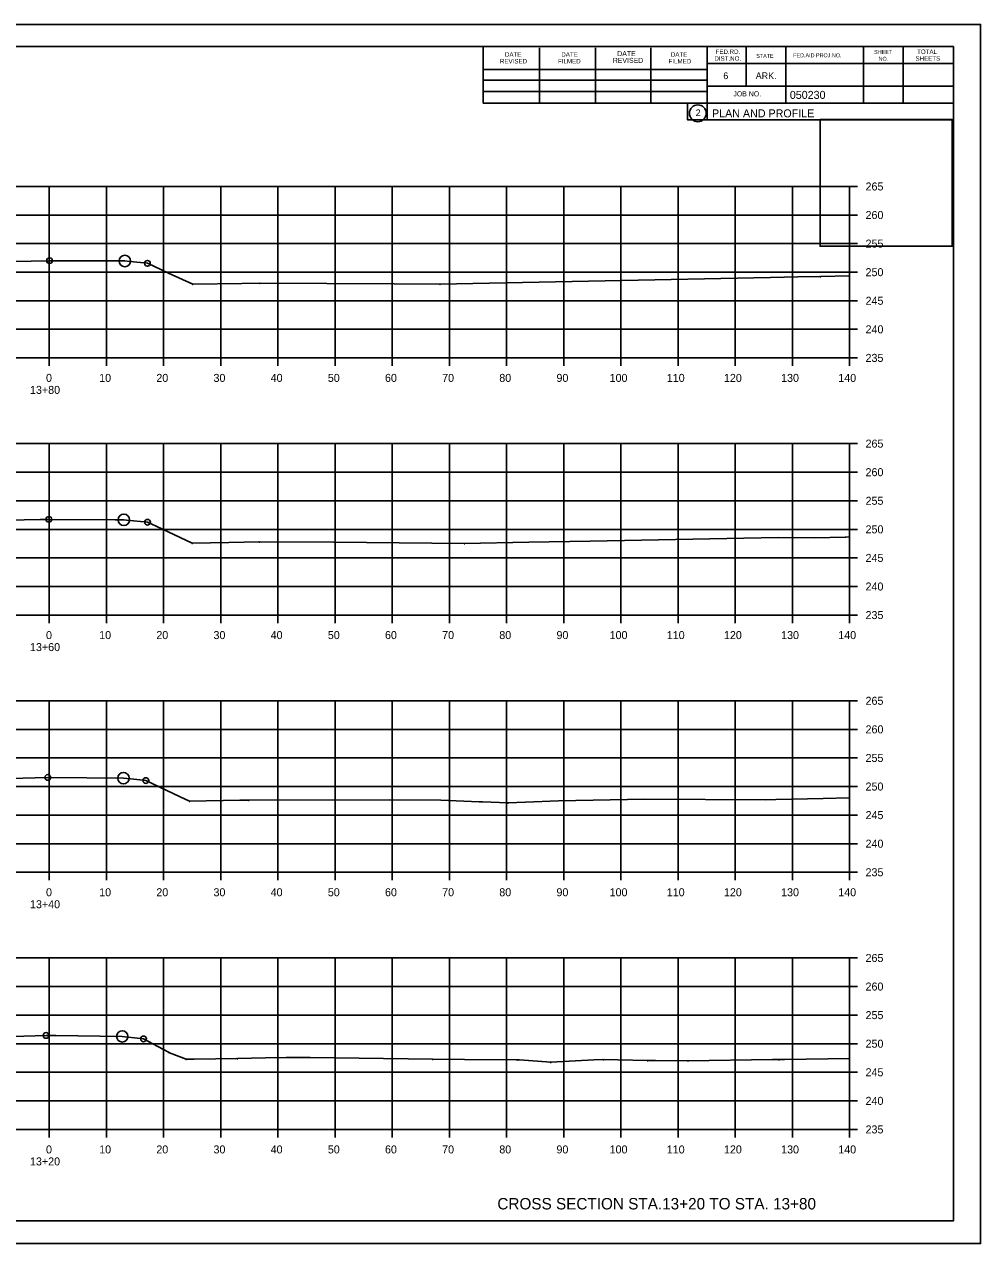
# Model space of a CAD drawing. Extents: x 1300404 to 1323571, y 234004 to 252077.
# Drawn here: x 1315712.9 to 1315880.2, y 244261.8 to 244475.2 of the extents above; entities that cross this region are included whole.
import ezdxf

# ---------------------------------------------------------------- set-up
doc = ezdxf.new("R2010")
doc.units = 0
for name, color, linetype in [('Default', 7, 'Continuous'), ('R_Axis', 7, 'Continuous'), ('R_Axis Annot', 7, 'Continuous'), ('R_Border', 7, 'Continuous'), ('R_Border Prem', 7, 'Continuous'), ('R_Draft', 7, 'Continuous'), ('R_Exist Surface', 7, 'Continuous'), ('R_Grid', 7, 'Continuous'), ('R_No Plot', 7, 'Continuous')]:
    doc.layers.add(name, color=color, linetype=linetype)

msp = doc.modelspace()

# ---------------------------------------------------------------- linework, layer by layer
at = {"layer": 'Default'}
for p, q in [((1315559.28, 244471.28), (1315875.46, 244471.28)), ((1315793.2, 244461.4), (1315793.2, 244471.28)), ((1315803.06, 244461.4), (1315803.06, 244471.08)), ((1315812.82, 244461.4), (1315812.82, 244471.08)), ((1315822.5, 244461.4), (1315822.5, 244471.08)), ((1315832.36, 244471.28), (1315832.36, 244458.48)), ((1315839.2, 244471.28), (1315839.2, 244464.34)), ((1315846.14, 244471.28), (1315846.14, 244461.4)), ((1315859.72, 244471.28), (1315859.72, 244461.4)), ((1315866.66, 244471.28), (1315866.66, 244461.4)), ((1315875.46, 244265.82), (1315875.46, 244471.28)), ((1315875.46, 244468.34), (1315832.36, 244468.34)), ((1315875.46, 244468.36), (1315875.46, 244468.36)), ((1315793.2, 244467.26), (1315832.36, 244467.26)), ((1315793.2, 244465.4), (1315832.36, 244465.4)), ((1315875.46, 244464.34), (1315832.36, 244464.34)), ((1315835.32, 244464.34), (1315875.46, 244464.34)), ((1315793.2, 244461.4), (1315793.2, 244463.46)), ((1315793.2, 244463.46), (1315832.36, 244463.46)), ((1315875.46, 244461.4), (1315793.2, 244461.4)), ((1315832.36, 244458.48), (1315875.46, 244458.48)), ((1315875.46, 244265.82), (1315559.28, 244265.82))]:
    msp.add_line(p, q, dxfattribs=at)
msp.add_circle((1315830.74, 244459.62), 1.47, dxfattribs=at)
at = {"layer": 'R_Axis'}
for p, q in [((1315857.28, 244416.82), (1315857.28, 244446.82)), ((1315858.68, 244446.82), (1315857.28, 244446.82)), ((1315858.68, 244441.82), (1315857.28, 244441.82)), ((1315858.68, 244436.82), (1315857.28, 244436.82)), ((1315858.68, 244431.82), (1315857.28, 244431.82)), ((1315858.68, 244426.82), (1315857.28, 244426.82)), ((1315858.68, 244421.82), (1315857.28, 244421.82)), ((1315577.28, 244416.82), (1315857.28, 244416.82)), ((1315717.28, 244415.42), (1315717.28, 244416.82)), ((1315727.28, 244415.42), (1315727.28, 244416.82)), ((1315737.28, 244415.42), (1315737.28, 244416.82)), ((1315747.28, 244415.42), (1315747.28, 244416.82)), ((1315757.28, 244415.42), (1315757.28, 244416.82)), ((1315767.28, 244415.42), (1315767.28, 244416.82)), ((1315777.28, 244415.42), (1315777.28, 244416.82)), ((1315787.28, 244415.42), (1315787.28, 244416.82)), ((1315797.28, 244415.42), (1315797.28, 244416.82)), ((1315807.28, 244415.42), (1315807.28, 244416.82)), ((1315817.28, 244415.42), (1315817.28, 244416.82)), ((1315827.28, 244415.42), (1315827.28, 244416.82)), ((1315837.28, 244415.42), (1315837.28, 244416.82)), ((1315847.28, 244415.42), (1315847.28, 244416.82)), ((1315857.28, 244415.42), (1315857.28, 244416.82)), ((1315858.68, 244416.82), (1315857.28, 244416.82)), ((1315857.28, 244371.82), (1315857.28, 244401.82)), ((1315858.68, 244401.82), (1315857.28, 244401.82)), ((1315858.68, 244396.82), (1315857.28, 244396.82)), ((1315858.68, 244391.82), (1315857.28, 244391.82)), ((1315858.68, 244386.82), (1315857.28, 244386.82)), ((1315858.68, 244381.82), (1315857.28, 244381.82)), ((1315858.68, 244376.82), (1315857.28, 244376.82)), ((1315577.28, 244371.82), (1315857.28, 244371.82)), ((1315717.28, 244370.42), (1315717.28, 244371.82)), ((1315727.28, 244370.42), (1315727.28, 244371.82)), ((1315737.28, 244370.42), (1315737.28, 244371.82)), ((1315747.28, 244370.42), (1315747.28, 244371.82)), ((1315757.28, 244370.42), (1315757.28, 244371.82)), ((1315767.28, 244370.42), (1315767.28, 244371.82)), ((1315777.28, 244370.42), (1315777.28, 244371.82)), ((1315787.28, 244370.42), (1315787.28, 244371.82)), ((1315797.28, 244370.42), (1315797.28, 244371.82)), ((1315807.28, 244370.42), (1315807.28, 244371.82)), ((1315817.28, 244370.42), (1315817.28, 244371.82)), ((1315827.28, 244370.42), (1315827.28, 244371.82)), ((1315837.28, 244370.42), (1315837.28, 244371.82)), ((1315847.28, 244370.42), (1315847.28, 244371.82)), ((1315857.28, 244370.42), (1315857.28, 244371.82)), ((1315858.68, 244371.82), (1315857.28, 244371.82)), ((1315857.28, 244326.82), (1315857.28, 244356.82)), ((1315858.68, 244356.82), (1315857.28, 244356.82)), ((1315858.68, 244351.82), (1315857.28, 244351.82)), ((1315858.68, 244346.82), (1315857.28, 244346.82)), ((1315858.68, 244341.82), (1315857.28, 244341.82)), ((1315858.68, 244336.82), (1315857.28, 244336.82)), ((1315858.68, 244331.82), (1315857.28, 244331.82)), ((1315577.28, 244326.82), (1315857.28, 244326.82)), ((1315717.28, 244325.42), (1315717.28, 244326.82)), ((1315727.28, 244325.42), (1315727.28, 244326.82)), ((1315737.28, 244325.42), (1315737.28, 244326.82)), ((1315747.28, 244325.42), (1315747.28, 244326.82)), ((1315757.28, 244325.42), (1315757.28, 244326.82)), ((1315767.28, 244325.42), (1315767.28, 244326.82)), ((1315777.28, 244325.42), (1315777.28, 244326.82)), ((1315787.28, 244325.42), (1315787.28, 244326.82)), ((1315797.28, 244325.42), (1315797.28, 244326.82)), ((1315807.28, 244325.42), (1315807.28, 244326.82)), ((1315817.28, 244325.42), (1315817.28, 244326.82)), ((1315827.28, 244325.42), (1315827.28, 244326.82)), ((1315837.28, 244325.42), (1315837.28, 244326.82)), ((1315847.28, 244325.42), (1315847.28, 244326.82)), ((1315857.28, 244325.42), (1315857.28, 244326.82)), ((1315858.68, 244326.82), (1315857.28, 244326.82)), ((1315857.28, 244281.82), (1315857.28, 244311.82)), ((1315858.68, 244311.82), (1315857.28, 244311.82)), ((1315858.68, 244306.82), (1315857.28, 244306.82)), ((1315858.68, 244301.82), (1315857.28, 244301.82)), ((1315858.68, 244296.82), (1315857.28, 244296.82)), ((1315858.68, 244291.82), (1315857.28, 244291.82)), ((1315858.68, 244286.82), (1315857.28, 244286.82)), ((1315577.28, 244281.82), (1315857.28, 244281.82)), ((1315717.28, 244280.42), (1315717.28, 244281.82)), ((1315727.28, 244280.42), (1315727.28, 244281.82)), ((1315737.28, 244280.42), (1315737.28, 244281.82)), ((1315747.28, 244280.42), (1315747.28, 244281.82)), ((1315757.28, 244280.42), (1315757.28, 244281.82)), ((1315767.28, 244280.42), (1315767.28, 244281.82)), ((1315777.28, 244280.42), (1315777.28, 244281.82)), ((1315787.28, 244280.42), (1315787.28, 244281.82)), ((1315797.28, 244280.42), (1315797.28, 244281.82)), ((1315807.28, 244280.42), (1315807.28, 244281.82)), ((1315817.28, 244280.42), (1315817.28, 244281.82)), ((1315827.28, 244280.42), (1315827.28, 244281.82)), ((1315837.28, 244280.42), (1315837.28, 244281.82)), ((1315847.28, 244280.42), (1315847.28, 244281.82)), ((1315857.28, 244280.42), (1315857.28, 244281.82)), ((1315858.68, 244281.82), (1315857.28, 244281.82))]:
    msp.add_line(p, q, dxfattribs=at)
at = {"layer": 'R_Draft'}
for points in [[(1315742.37, 244429.77), (1315742.42, 244429.67), (1315742.32, 244429.67)], [(1315754.08, 244429.94), (1315754.13, 244429.84), (1315754.03, 244429.84)], [(1315785.63, 244429.77), (1315785.68, 244429.67), (1315785.58, 244429.67)], [(1315852.2, 244431.1), (1315852.25, 244431), (1315852.15, 244431)], [(1315754.07, 244384.7), (1315754.12, 244384.6), (1315754.02, 244384.6)], [(1315856.55, 244385.53), (1315856.6, 244385.43), (1315856.5, 244385.43)], [(1315742.29, 244384.47), (1315742.34, 244384.37), (1315742.24, 244384.37)], [(1315789.92, 244384.39), (1315789.97, 244384.29), (1315789.87, 244384.29)], [(1315741.82, 244339.31), (1315741.87, 244339.21), (1315741.77, 244339.21)], [(1315752.19, 244339.49), (1315752.24, 244339.39), (1315752.14, 244339.39)], [(1315797.54, 244339.01), (1315797.59, 244338.91), (1315797.49, 244338.91)], [(1315738.23, 244295.34), (1315738.28, 244295.24), (1315738.18, 244295.24)], [(1315741.22, 244294.15), (1315741.27, 244294.05), (1315741.17, 244294.05)], [(1315750.19, 244294.29), (1315750.24, 244294.19), (1315750.14, 244294.19)], [(1315784.32, 244294.18), (1315784.37, 244294.08), (1315784.27, 244294.08)], [(1315799.1, 244294.06), (1315799.15, 244293.96), (1315799.05, 244293.96)], [(1315805.01, 244293.62), (1315805.06, 244293.52), (1315804.96, 244293.52)], [(1315814.23, 244294.1), (1315814.28, 244294), (1315814.18, 244294)], [(1315821.95, 244293.94), (1315822, 244293.84), (1315821.9, 244293.84)], [(1315829.02, 244293.89), (1315829.07, 244293.79), (1315828.97, 244293.79)], [(1315844.92, 244294.09), (1315844.97, 244293.99), (1315844.87, 244293.99)]]:
    msp.add_lwpolyline(points, close=True, dxfattribs=at)
at = {"layer": 'R_Exist Surface'}
for points in [[(1315707.71, 244433.64), (1315717.34, 244433.83), (1315727.31, 244433.79), (1315730.49, 244433.78), (1315731.4, 244433.68), (1315734.45, 244433.37), (1315738.16, 244431.67), (1315742.37, 244429.72), (1315750.97, 244429.83), (1315754.08, 244429.89), (1315777.6, 244429.78), (1315785.63, 244429.72), (1315843.43, 244430.89), (1315848.26, 244430.98), (1315852.2, 244431.05), (1315857.28, 244431.16)], [(1315704.45, 244388.29), (1315715.7, 244388.54), (1315717.2, 244388.57), (1315728.83, 244388.49), (1315730.33, 244388.48), (1315730.78, 244388.43), (1315734.47, 244388.06), (1315735.97, 244387.37), (1315742.29, 244384.42), (1315748.68, 244384.54), (1315754.07, 244384.65), (1315767.04, 244384.56), (1315789.92, 244384.34), (1315801.17, 244384.56), (1315811.92, 244384.74), (1315844.77, 244385.39), (1315851.09, 244385.35), (1315856.55, 244385.48), (1315857.28, 244385.5)], [(1315710.45, 244343.24), (1315717.01, 244343.41), (1315723.86, 244343.36), (1315730.25, 244343.29), (1315732.1, 244343.08), (1315734.18, 244342.86), (1315740.18, 244340.03), (1315741.82, 244339.26), (1315750.59, 244339.41), (1315752.19, 244339.44), (1315776.72, 244339.5), (1315785.77, 244339.43), (1315792.48, 244339.16), (1315793.07, 244339.15), (1315797.54, 244338.96), (1315800.57, 244339.07), (1315806.39, 244339.29), (1315821.45, 244339.58), (1315842.63, 244339.48), (1315844.38, 244339.53), (1315852.67, 244339.73), (1315857.28, 244339.84)], [(1315705, 244297.91), (1315716.71, 244298.26), (1315718.43, 244298.24), (1315730.05, 244298.1), (1315733.25, 244297.71), (1315733.77, 244297.65), (1315737.14, 244295.85), (1315738.23, 244295.29), (1315738.33, 244295.24), (1315741.22, 244294.1), (1315742.62, 244294.12), (1315750.19, 244294.24), (1315755.09, 244294.34), (1315758.72, 244294.41), (1315762.94, 244294.42), (1315784.32, 244294.13), (1315789.91, 244294.08), (1315799.1, 244294.01), (1315799.56, 244293.99), (1315805.01, 244293.57), (1315812.54, 244294.01), (1315814.23, 244294.05), (1315816.76, 244294.02), (1315821.95, 244293.89), (1315823.35, 244293.88), (1315829.02, 244293.84), (1315843.81, 244294.03), (1315844.92, 244294.04), (1315845.89, 244294.06), (1315857.28, 244294.24)]]:
    msp.add_lwpolyline(points, dxfattribs=at)
at = {"layer": 'R_Grid'}
for p, q in [((1315577.28, 244446.82), (1315857.28, 244446.82)), ((1315717.28, 244416.82), (1315717.28, 244446.82)), ((1315727.28, 244416.82), (1315727.28, 244446.82)), ((1315737.28, 244416.82), (1315737.28, 244446.82)), ((1315747.28, 244416.82), (1315747.28, 244446.82)), ((1315757.28, 244416.82), (1315757.28, 244446.82)), ((1315767.28, 244416.82), (1315767.28, 244446.82)), ((1315777.28, 244416.82), (1315777.28, 244446.82)), ((1315787.28, 244416.82), (1315787.28, 244446.82)), ((1315797.28, 244416.82), (1315797.28, 244446.82)), ((1315807.28, 244416.82), (1315807.28, 244446.82)), ((1315817.28, 244416.82), (1315817.28, 244446.82)), ((1315827.28, 244416.82), (1315827.28, 244446.82)), ((1315837.28, 244416.82), (1315837.28, 244446.82)), ((1315847.28, 244416.82), (1315847.28, 244446.82)), ((1315857.28, 244416.82), (1315857.28, 244446.82)), ((1315577.28, 244441.82), (1315857.28, 244441.82)), ((1315577.28, 244436.82), (1315857.28, 244436.82)), ((1315577.28, 244431.82), (1315857.28, 244431.82)), ((1315577.28, 244426.82), (1315857.28, 244426.82)), ((1315577.28, 244421.82), (1315857.28, 244421.82)), ((1315577.28, 244416.82), (1315857.28, 244416.82)), ((1315577.28, 244401.82), (1315857.28, 244401.82)), ((1315717.28, 244371.82), (1315717.28, 244401.82)), ((1315727.28, 244371.82), (1315727.28, 244401.82)), ((1315737.28, 244371.82), (1315737.28, 244401.82)), ((1315747.28, 244371.82), (1315747.28, 244401.82)), ((1315757.28, 244371.82), (1315757.28, 244401.82)), ((1315767.28, 244371.82), (1315767.28, 244401.82)), ((1315777.28, 244371.82), (1315777.28, 244401.82)), ((1315787.28, 244371.82), (1315787.28, 244401.82)), ((1315797.28, 244371.82), (1315797.28, 244401.82)), ((1315807.28, 244371.82), (1315807.28, 244401.82)), ((1315817.28, 244371.82), (1315817.28, 244401.82)), ((1315827.28, 244371.82), (1315827.28, 244401.82)), ((1315837.28, 244371.82), (1315837.28, 244401.82)), ((1315847.28, 244371.82), (1315847.28, 244401.82)), ((1315857.28, 244371.82), (1315857.28, 244401.82)), ((1315577.28, 244396.82), (1315857.28, 244396.82)), ((1315577.28, 244391.82), (1315857.28, 244391.82)), ((1315577.28, 244386.82), (1315857.28, 244386.82)), ((1315577.28, 244381.82), (1315857.28, 244381.82)), ((1315577.28, 244376.82), (1315857.28, 244376.82)), ((1315577.28, 244371.82), (1315857.28, 244371.82)), ((1315577.28, 244356.82), (1315857.28, 244356.82)), ((1315717.28, 244326.82), (1315717.28, 244356.82)), ((1315727.28, 244326.82), (1315727.28, 244356.82)), ((1315737.28, 244326.82), (1315737.28, 244356.82)), ((1315747.28, 244326.82), (1315747.28, 244356.82)), ((1315757.28, 244326.82), (1315757.28, 244356.82)), ((1315767.28, 244326.82), (1315767.28, 244356.82)), ((1315777.28, 244326.82), (1315777.28, 244356.82)), ((1315787.28, 244326.82), (1315787.28, 244356.82)), ((1315797.28, 244326.82), (1315797.28, 244356.82)), ((1315807.28, 244326.82), (1315807.28, 244356.82)), ((1315817.28, 244326.82), (1315817.28, 244356.82)), ((1315827.28, 244326.82), (1315827.28, 244356.82)), ((1315837.28, 244326.82), (1315837.28, 244356.82)), ((1315847.28, 244326.82), (1315847.28, 244356.82)), ((1315857.28, 244326.82), (1315857.28, 244356.82)), ((1315577.28, 244351.82), (1315857.28, 244351.82)), ((1315577.28, 244346.82), (1315857.28, 244346.82)), ((1315577.28, 244341.82), (1315857.28, 244341.82)), ((1315577.28, 244336.82), (1315857.28, 244336.82)), ((1315577.28, 244331.82), (1315857.28, 244331.82)), ((1315577.28, 244326.82), (1315857.28, 244326.82)), ((1315577.28, 244311.82), (1315857.28, 244311.82)), ((1315717.28, 244281.82), (1315717.28, 244311.82)), ((1315727.28, 244281.82), (1315727.28, 244311.82)), ((1315737.28, 244281.82), (1315737.28, 244311.82)), ((1315747.28, 244281.82), (1315747.28, 244311.82)), ((1315757.28, 244281.82), (1315757.28, 244311.82)), ((1315767.28, 244281.82), (1315767.28, 244311.82)), ((1315777.28, 244281.82), (1315777.28, 244311.82)), ((1315787.28, 244281.82), (1315787.28, 244311.82)), ((1315797.28, 244281.82), (1315797.28, 244311.82)), ((1315807.28, 244281.82), (1315807.28, 244311.82)), ((1315817.28, 244281.82), (1315817.28, 244311.82)), ((1315827.28, 244281.82), (1315827.28, 244311.82)), ((1315837.28, 244281.82), (1315837.28, 244311.82)), ((1315847.28, 244281.82), (1315847.28, 244311.82)), ((1315857.28, 244281.82), (1315857.28, 244311.82)), ((1315577.28, 244306.82), (1315857.28, 244306.82)), ((1315577.28, 244301.82), (1315857.28, 244301.82)), ((1315577.28, 244296.82), (1315857.28, 244296.82)), ((1315577.28, 244291.82), (1315857.28, 244291.82)), ((1315577.28, 244286.82), (1315857.28, 244286.82)), ((1315577.28, 244281.82), (1315857.28, 244281.82))]:
    msp.add_line(p, q, dxfattribs=at)
at = {"layer": 'R_No Plot'}
for p, q in [((1315546.87, 244475.18), (1315880.21, 244475.18)), ((1315546.87, 244261.84), (1315880.21, 244261.84))]:
    msp.add_line(p, q, dxfattribs=at)
for points in [[(1315546.87, 244475.18), (1315880.21, 244475.18), (1315880.21, 244261.84), (1315546.87, 244261.84)], [(1315793.2, 244471.28), (1315793.2, 244461.4), (1315828.93, 244461.4), (1315828.93, 244458.48), (1315852.13, 244458.48), (1315852.13, 244436.36), (1315875.46, 244436.36), (1315875.46, 244265.82), (1315559.28, 244265.82), (1315559.28, 244471.28)], [(1315852.13, 244458.51), (1315875.23, 244458.51), (1315875.23, 244436.36), (1315852.13, 244436.36)]]:
    msp.add_lwpolyline(points, close=True, dxfattribs=at)
for centre, radius in [((1315717.34, 244433.83), 0.5), ((1315730.49, 244433.78), 1), ((1315734.45, 244433.37), 0.5), ((1315717.2, 244388.57), 0.5), ((1315730.33, 244388.48), 1), ((1315734.47, 244388.06), 0.5), ((1315730.25, 244343.29), 1), ((1315717.01, 244343.41), 0.5), ((1315734.18, 244342.86), 0.5), ((1315716.71, 244298.26), 0.5), ((1315730.05, 244298.1), 1), ((1315733.77, 244297.65), 0.5)]:
    msp.add_circle(centre, radius, dxfattribs=at)

# ---------------------------------------------------------------- texts
at = {"layer": 'Default'}
msp.add_text('2', height=1.17, dxfattribs=at).set_placement((1315830.36, 244459.13))
at = {"layer": 'R_Axis Annot'}
for s, p in [('265', (1315860.08, 244446.12)), ('260', (1315860.08, 244441.12)), ('255', (1315860.08, 244436.12)), ('250', (1315860.08, 244431.12)), ('245', (1315860.08, 244426.12)), ('240', (1315860.08, 244421.12)), ('235', (1315860.08, 244416.12)), ('0', (1315716.71, 244412.62)), ('10', (1315726.01, 244412.62)), ('20', (1315736.01, 244412.62)), ('30', (1315746.01, 244412.62)), ('40', (1315756.01, 244412.62)), ('50', (1315766.01, 244412.62)), ('60', (1315776.01, 244412.62)), ('70', (1315786.01, 244412.62)), ('80', (1315796.01, 244412.62)), ('90', (1315806.01, 244412.62)), ('100', (1315815.31, 244412.62)), ('110', (1315825.31, 244412.62)), ('120', (1315835.31, 244412.62)), ('130', (1315845.31, 244412.62)), ('140', (1315855.31, 244412.62)), ('13+80', (1315713.91, 244410.52)), ('265', (1315860.08, 244401.12)), ('260', (1315860.08, 244396.12)), ('255', (1315860.08, 244391.12)), ('250', (1315860.08, 244386.12)), ('245', (1315860.08, 244381.12)), ('240', (1315860.08, 244376.12)), ('235', (1315860.08, 244371.12)), ('0', (1315716.71, 244367.62)), ('10', (1315726.01, 244367.62)), ('20', (1315736.01, 244367.62)), ('30', (1315746.01, 244367.62)), ('40', (1315756.01, 244367.62)), ('50', (1315766.01, 244367.62)), ('60', (1315776.01, 244367.62)), ('70', (1315786.01, 244367.62)), ('80', (1315796.01, 244367.62)), ('90', (1315806.01, 244367.62)), ('100', (1315815.31, 244367.62)), ('110', (1315825.31, 244367.62)), ('120', (1315835.31, 244367.62)), ('130', (1315845.31, 244367.62)), ('140', (1315855.31, 244367.62)), ('13+60', (1315713.91, 244365.52)), ('265', (1315860.08, 244356.12)), ('260', (1315860.08, 244351.12)), ('255', (1315860.08, 244346.12)), ('250', (1315860.08, 244341.12)), ('245', (1315860.08, 244336.12)), ('240', (1315860.08, 244331.12)), ('235', (1315860.08, 244326.12)), ('0', (1315716.71, 244322.62)), ('10', (1315726.01, 244322.62)), ('20', (1315736.01, 244322.62)), ('30', (1315746.01, 244322.62)), ('40', (1315756.01, 244322.62)), ('50', (1315766.01, 244322.62)), ('60', (1315776.01, 244322.62)), ('70', (1315786.01, 244322.62)), ('80', (1315796.01, 244322.62)), ('90', (1315806.01, 244322.62)), ('100', (1315815.31, 244322.62)), ('110', (1315825.31, 244322.62)), ('120', (1315835.31, 244322.62)), ('130', (1315845.31, 244322.62)), ('140', (1315855.31, 244322.62)), ('13+40', (1315713.91, 244320.52)), ('265', (1315860.08, 244311.12)), ('260', (1315860.08, 244306.12)), ('255', (1315860.08, 244301.12)), ('250', (1315860.08, 244296.12)), ('245', (1315860.08, 244291.12)), ('240', (1315860.08, 244286.12)), ('235', (1315860.08, 244281.12)), ('0', (1315716.71, 244277.62)), ('10', (1315726.01, 244277.62)), ('20', (1315736.01, 244277.62)), ('30', (1315746.01, 244277.62)), ('40', (1315756.01, 244277.62)), ('50', (1315766.01, 244277.62)), ('60', (1315776.01, 244277.62)), ('70', (1315786.01, 244277.62)), ('80', (1315796.01, 244277.62)), ('90', (1315806.01, 244277.62)), ('100', (1315815.31, 244277.62)), ('110', (1315825.31, 244277.62)), ('120', (1315835.31, 244277.62)), ('130', (1315845.31, 244277.62)), ('140', (1315855.31, 244277.62)), ('13+20', (1315713.91, 244275.52))]:
    msp.add_text(s, height=1.4, dxfattribs=at).set_placement(p)
at = {"layer": 'R_Border'}
for s, height, p in [('DATE', 0.782, (1315797, 244469.52)), ('DATE', 0.782, (1315806.86, 244469.52)), ('DATE', 0.879, (1315816.64, 244469.62)), ('DATE', 0.782, (1315826.02, 244469.52)), ('FED.RD.', 0.782, (1315833.84, 244470)), ('STATE', 0.684, (1315840.96, 244469.32)), ('FED.AID PROJ.NO.', 0.684, (1315847.42, 244469.42)), ('SHEET', 0.684, (1315861.58, 244470)), ('TOTAL', 0.782, (1315869.1, 244470)), ('REVISED', 0.782, (1315796.12, 244468.34)), ('FILMED', 0.782, (1315806.28, 244468.34)), ('REVISED', 0.879, (1315815.86, 244468.44)), ('FILMED', 0.782, (1315825.62, 244468.34)), ('DIST.NO.', 0.782, (1315833.64, 244468.82)), ('NO.', 0.684, (1315862.36, 244468.82)), ('SHEETS', 0.782, (1315868.82, 244468.82)), ('6', 1.17, (1315835.2, 244465.6)), ('ARK.', 1.172, (1315840.86, 244465.6)), ('JOB NO.', 0.879, (1315836.96, 244462.58))]:
    msp.add_text(s, height=height, dxfattribs=at).set_placement(p)
for s, p in [('050230', (1315846.83, 244462.14)), ('PLAN AND PROFILE', (1315833.22, 244458.91))]:
    msp.add_text(s, height=1.4, rotation=360, dxfattribs=at).set_placement(p)
at = {"layer": 'R_Border Prem'}
msp.add_text('DWB', height=0.01, dxfattribs=at).set_placement((1315836.15, 244452.79))
at = {"layer": 'R_Draft'}
msp.add_text('CROSS SECTION STA.13+20 TO STA. 13+80', height=2, dxfattribs=at).set_placement((1315795.67, 244267.82))

doc.saveas('drawing.dxf')
